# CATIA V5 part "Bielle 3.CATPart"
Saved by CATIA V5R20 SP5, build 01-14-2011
Part number: Bielle 3
Bounding box of the stored display mesh (mm): x -220 to 220, y -16.108 to 7.737, z 59.806 to 125.755
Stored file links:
  F:\Travaux\Modélisations\CFAO_2011\MMS\MMS_GR2\AA_OK\tquattrone\Catia\Bielle 3.CATPart
  C:\Users\Tom\Documents\Cours 2A\CFAO\Projet thinkmotion\Aileron_citroen.CATProduct
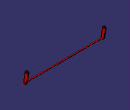
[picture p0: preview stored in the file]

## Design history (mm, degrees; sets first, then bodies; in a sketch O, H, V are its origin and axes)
Parameters
  Epaisseur_bielle_3 = 5 mm
  `Diamètre_trou_bielle3` = 6 mm
Set1
  Plane1 "Plan_bielle2/3": linked copy from another document
  Point1 "Point_bielle_12": linked copy from another document
  Point2 "Point_bielle_32": linked copy from another document
  Point3 "Point_bielle_31": linked copy from another document
  Plane2 "Plan_sym": linked copy from another document
  Plane3 "Plan_bielle1": linked copy from another document
Body1 (main body)
  Sketch1 on Plane1, origin (210, 0, 0), H (0, 1, 0), V (0, 0, 1)
    line L1 (-7.7726, 119.2677) -> (-16.108, 68.1593)
    arc A1 centre (-9, 67) radius 7.202 from (-16.108, 68.1593) to (-1.9245, 65.6563) ccw
    point P3 (-9, 67)
    line L2 (-1.9245, 65.6563) -> (7.737, 116.5307)
    arc A2 centre (0, 118) radius 7.8753 from (7.737, 116.5307) to (-7.7726, 119.2677) ccw
    point P6 (0, 118)
    reference projected point E1 (-9, 67) from Point1
    reference projected point E2 (0, 118) from Point2
    circle A3 centre (0, 118) radius 3
    point P7 (0, 118)
    reference projected point E3 (0, 118) from Point2
    radius A3 = 3 {= `Diamètre_trou_bielle3` /2}
    tangency: A1 L1, L2 A1, A2 L1, A2 L2
    coincidence: P3 E1, P6 E2, P7 E3
  Pad1: profile Sketch1, direction (1, 0, 0), length 5 {= Epaisseur_bielle_3}
  Sketch2 on start face of Pad1, origin (210, 0, 0), H (0, -1, 0), V (0, 0, 1)
    circle A1 centre (9, 67) radius 3
    point P1 (9, 67)
    reference projected point E1 (9, 67) from Point1
    radius A1 = 3 {= `Diamètre_trou_bielle3` /2}
    coincidence: P1 E1
  Pad2: profile Sketch2, direction (-1, 0, 0), up to Plane2, opposite side up to Plane3
  Mirror1: of the body so far, about Plane2
  Point4: type Center, Curve edge [face of Pad2 from Sketch2.A1 | start face of Pad2]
